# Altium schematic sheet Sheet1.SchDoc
size A4
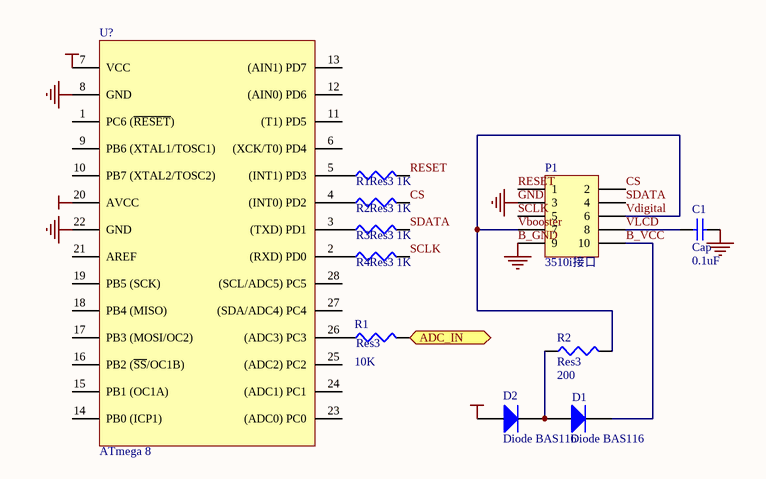
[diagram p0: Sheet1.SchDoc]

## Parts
(Parts that share a designator on the sheet are numbered #1, #2 ... from top to bottom, then left to right.)
C1  Cap  value 0.1uF  [RAD-0.3]
D1  Diode BAS116  [SO-G3/C2.5]
D2  Diode BAS116  [SO-G3/C2.5]
P1  3510i接口  [HDR2X5]
R1#1  Res3  value 1K  [C1608-0603]
R1#2  Res3  value 10K  [C1608-0603]
R2#1  Res3  value 1K  [C1608-0603]
R2#2  Res3  value 200  [C1608-0603]
R3  Res3  value 1K  [C1608-0603]
R4  Res3  value 1K  [C1608-0603]
U?  ATmega 8  [底座DIP-28/引脚7.62mm]

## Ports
ADC_IN

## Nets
B_GND: C1.2 P1.3 P1.9 U?.8(GND) U?.22(GND)  [also labelled GND]
VCC: D2.1(A) U?.7(VCC) U?.20(AVCC)
ADC_IN: R1#2.2 ; port ADC_IN
B_VCC: D1.3(K) P1.10
CS: P1.2 R2#1.2
RESET: P1.1 R1#1.2
SCLK: P1.5 R4.2
SDATA: P1.4 R3.2
Vbooster: P1.6 P1.7 R2#2.2  [also labelled Vdigital ]
VLCD: C1.1 P1.8
NetD1_1: D1.1(A) D2.3(K) R2#2.1
NetR1#1_1: R1#1.1 U?.5((INT1)_PD3)
NetR1#2_1: R1#2.1 U?.26((ADC3)_PC3)
NetR2#1_1: R2#1.1 U?.4((INT0)_PD2)
NetR3_1: R3.1 U?.3((TXD)_PD1)
NetR4_1: R4.1 U?.2((RXD)_PD0)

Not connected (* = marked no-connect by the designer): U? 1(PC6_(~{RESET})) 6((XCK/T0)_PD4) 9(PB6_(XTAL1/TOSC1)) 10(PB7_(XTAL2/TOSC2)) 11((T1)_PD5) 12((AIN0)_PD6) 13((AIN1)_PD7) 14(PB0_(ICP1)) 15(PB1_(OC1A)) 16(PB2_(~{SS}/OC1B)) 17(PB3_(MOSI/OC2)) 18(PB4_(MISO)) 19(PB5_(SCK)) 21(AREF) 23((ADC0)_PC0) 24((ADC1)_PC1) 25((ADC2)_PC2) 27((SDA/ADC4)_PC4) 28((SCL/ADC5)_PC5)

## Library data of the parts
C1 = Cap: Capacitor
D1 D2 = Diode BAS116: Silicon Low Leakage Diode; Note: Pin 2 is not connected and not drawn.
P1 = Header 5X2: Header, 5-Pin, Dual row
R1#1 R1#2 R2#1 R2#2 R3 R4 = Res3: Resistor
U? = ATmega8/28引脚: 8 位微处理器/28引脚; 子类别: 微处理器; 发布者: 磊元工作室; 发布日期: 2003年8月18日; 制造商: Atmel Corporation; 类别: 集成电路; 元件名称（国标）: 8 位微处理器; 元件名称（英文）: 8-bit Microcontroller; 特性:存储器容量: Flash：8KB ，EEPROM：512B ，RAM：1KB; 特性:定时器/计数器: 2 个 8-bit ，1 个 16-bit; 特性:模/数转换器: 6 通道 10-bit ADC; 特性:指令: 两个时钟周期的硬件乘法器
